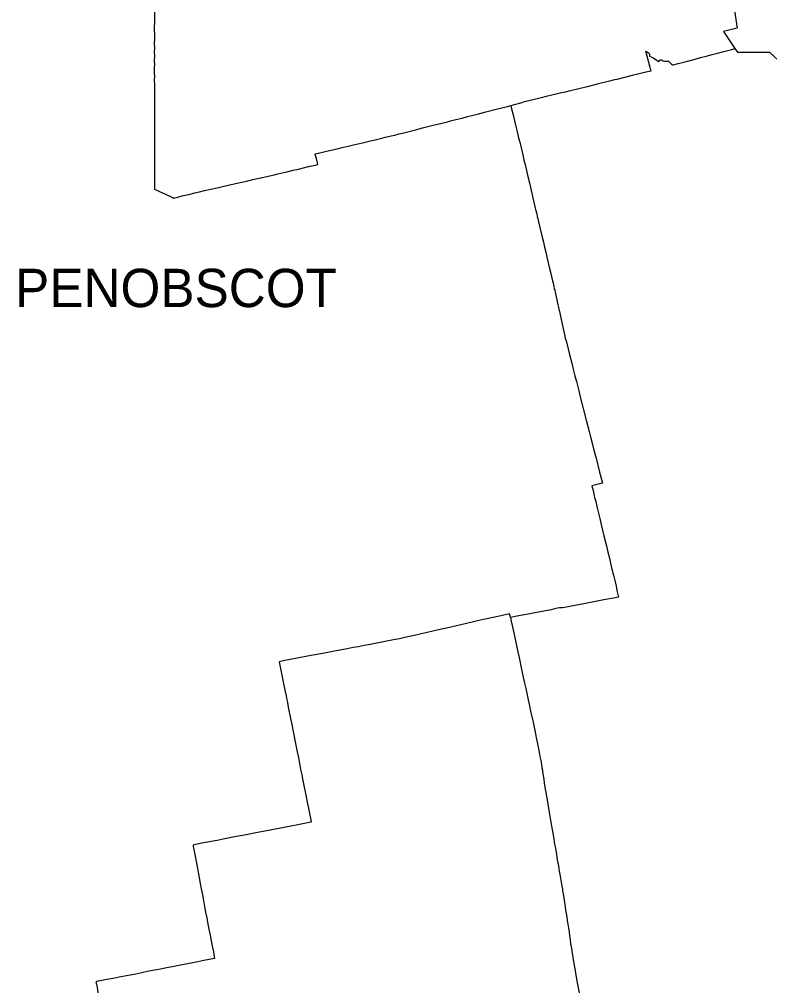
# Model space of a CAD drawing. Extents: x 1104458 to 2179854, y 15641624 to 17244911.
# Drawn here: x 1748405 to 1955164, y 16340321 to 16606552 of the extents above; entities that cross this region are included whole.
import ezdxf

# ---------------------------------------------------------------- set-up
doc = ezdxf.new("R2010")
doc.units = 0
doc.layers.add('ANNOTATION', color=7, linetype='Continuous')
doc.layers.add('CO BORDER', color=7, linetype='Continuous')

msp = doc.modelspace()

# ---------------------------------------------------------------- linework, layer by layer
at = {"layer": 'CO BORDER'}
msp.add_line((1909105, 16478728), (1906145, 16478068), dxfattribs=at)
for points in [[(1945334, 16632107), (1945226, 16630943), (1944313, 16630103), (1945087, 16625706), (1948488, 16623991), (1948540, 16623807), (1951451, 16616973), (1944329, 16616169), (1946216, 16604113), (1942463, 16603170), (1945597, 16598477)], [(1785548, 16625497), (1785552, 16624453), (1785582, 16622061), (1785592, 16618508), (1785601, 16617019), (1785608, 16613751), (1785598, 16612524), (1785621, 16610598), (1785629, 16609315), (1785620, 16605939), (1785599, 16604204), (1785628, 16601828), (1785622, 16600978), (1785593, 16599961), (1785608, 16598679), (1785605, 16597642), (1785618, 16596510), (1785604, 16595007), (1785614, 16594184), (1785600, 16593232), (1785583, 16592573), (1785596, 16592215)], [(1920987, 16597803), (1921302, 16596494), (1922109, 16593390), (1922410, 16592310), (1921539, 16592107), (1920286, 16591795), (1918844, 16591428), (1917276, 16591054), (1915568, 16590634), (1913011, 16590014)], [(1920987, 16597803), (1921258, 16597701), (1921889, 16597268), (1921965, 16597169), (1922018, 16596992), (1922024, 16596477), (1922083, 16596428), (1922914, 16596037), (1923283, 16595834), (1923645, 16595581), (1923788, 16595444), (1924150, 16595198), (1924420, 16594968), (1924537, 16594961), (1924669, 16595020), (1924915, 16595299), (1925073, 16595385), (1925272, 16595421), (1925373, 16595404), (1925826, 16595135), (1926160, 16595066), (1927019, 16595050), (1927286, 16594988), (1927463, 16594866), (1928139, 16594200), (1928379, 16593990), (1928551, 16594026), (1929986, 16594381), (1931470, 16594781), (1934637, 16595606), (1936071, 16595990), (1937704, 16596413), (1939321, 16596849), (1940772, 16597214), (1942173, 16597578), (1944776, 16598277), (1945597, 16598477)], [(1945597, 16598477), (1946273, 16597463), (1955132, 16597486), (1958877, 16593975)], [(1785596, 16592215), (1785585, 16591733), (1785613, 16590850), (1785601, 16589758), (1785633, 16588482), (1785627, 16587632), (1785634, 16586356), (1785619, 16584830), (1785632, 16581703), (1785641, 16578294), (1785638, 16577110), (1785655, 16575135), (1785646, 16573760), (1785656, 16570942), (1785648, 16568790), (1785662, 16567658), (1785650, 16566598), (1785653, 16565647), (1785669, 16564331), (1785661, 16563029), (1785680, 16561454), (1785672, 16560036), (1785684, 16559780), (1785835, 16559698), (1786521, 16559390), (1787183, 16559055)], [(1913011, 16590014), (1912400, 16589866), (1911065, 16589528), (1907955, 16588754), (1906222, 16588311), (1904853, 16587989), (1901843, 16587241), (1900233, 16586858), (1898771, 16586497), (1897459, 16586185), (1896293, 16585929), (1893569, 16585247), (1892166, 16584912), (1890687, 16584587), (1889175, 16584220), (1887267, 16583705)], [(1883855, 16582789), (1884808, 16583052), (1886992, 16583603), (1887267, 16583705)], [(1853530, 16575119), (1854714, 16575381), (1857968, 16576221), (1859530, 16576615), (1860941, 16576989), (1862461, 16577359), (1865990, 16578249), (1866398, 16578337), (1867187, 16578541), (1868656, 16578931), (1870392, 16579361), (1871911, 16579771), (1873481, 16580181), (1875001, 16580558), (1876628, 16580978), (1879767, 16581756), (1881030, 16582081), (1882931, 16582579), (1883855, 16582789)], [(1883855, 16582789), (1884057, 16581917), (1884461, 16580237), (1884847, 16578600), (1885232, 16577071), (1885592, 16575575), (1885995, 16573937), (1886286, 16572664), (1886758, 16570785), (1887119, 16569256), (1887428, 16567776), (1887760, 16566546), (1888542, 16563212), (1888963, 16561467), (1889245, 16560204), (1890387, 16555332), (1890660, 16554118), (1890965, 16552996), (1891125, 16552215), (1891257, 16551624), (1891362, 16551217)], [(1830654, 16566541), (1830584, 16566980), (1830253, 16568188), (1830043, 16569034), (1829962, 16569457), (1830369, 16569572), (1831532, 16569861), (1832703, 16570143), (1833891, 16570422), (1836026, 16570898), (1837330, 16571206), (1838999, 16571593), (1840511, 16571934), (1842106, 16572305), (1842978, 16572515), (1844041, 16572786), (1845179, 16573052), (1846425, 16573367), (1848277, 16573823), (1849257, 16574042), (1850088, 16574236), (1850840, 16574430)], [(1850840, 16574430), (1851857, 16574663), (1853077, 16574977), (1853530, 16575119)], [(1819674, 16564011), (1822141, 16564562), (1823819, 16564966), (1825289, 16565301), (1828437, 16566055), (1830041, 16566416), (1830654, 16566541)], [(1790819, 16557348), (1791275, 16557394), (1792080, 16557587), (1793575, 16557981), (1795129, 16558332), (1796739, 16558726), (1798085, 16559044), (1799472, 16559408), (1801159, 16559772), (1802929, 16560117), (1804415, 16560494), (1808760, 16561495), (1810629, 16561918), (1811393, 16562059), (1812755, 16562410), (1815347, 16563017), (1816601, 16563296), (1818637, 16563739), (1819674, 16564011)], [(1787183, 16559055), (1787719, 16558813), (1788699, 16558357), (1790425, 16557518), (1790702, 16557374), (1790819, 16557348)], [(1891362, 16551217), (1891493, 16550751), (1891861, 16549231), (1892493, 16546554), (1892844, 16545123), (1893144, 16543768), (1893477, 16542374), (1893794, 16540986), (1894129, 16539480), (1894514, 16537908), (1894823, 16536527), (1895218, 16534900), (1895480, 16533850), (1895674, 16532987), (1895814, 16532429), (1895945, 16531947), (1896072, 16531412), (1896533, 16529253), (1896800, 16527902), (1897038, 16526753), (1897403, 16525228), (1897706, 16523824), (1898607, 16519723)], [(1898607, 16519723), (1898845, 16518696), (1899141, 16517665), (1899912, 16514588), (1900735, 16511428), (1901061, 16510146), (1901506, 16508361), (1901931, 16506753), (1902294, 16505316), (1902558, 16504220), (1903057, 16502222), (1904607, 16496100), (1905422, 16492957), (1905785, 16491517), (1906219, 16489824), (1906661, 16488183), (1907314, 16485618), (1908200, 16482186), (1908808, 16479788), (1909105, 16478728)], [(1906145, 16478068), (1906483, 16476773), (1906921, 16474827), (1907218, 16473708), (1907536, 16472330), (1908368, 16469026), (1908750, 16467356), (1909502, 16464295), (1909911, 16462550), (1910271, 16461156), (1910583, 16459712), (1910982, 16458068), (1911333, 16456733), (1911708, 16455053), (1912098, 16453403), (1912461, 16451926), (1912824, 16450371), (1913162, 16448846), (1913540, 16447389)], [(1913540, 16447389), (1913018, 16447277), (1912155, 16447110), (1910479, 16446818), (1909011, 16446497), (1903958, 16445552), (1901445, 16445066), (1899629, 16444705), (1898085, 16444423), (1897425, 16444436), (1897140, 16444384)], [(1883704, 16441775), (1883616, 16442231), (1883511, 16442737), (1881061, 16442223), (1879417, 16441862), (1876272, 16441190), (1874687, 16440819), (1873168, 16440481), (1870097, 16439753), (1868511, 16439392), (1866975, 16439031), (1863903, 16438329), (1862317, 16437981), (1860756, 16437623), (1859236, 16437266), (1857650, 16436915), (1854594, 16436206), (1853165, 16435885), (1851521, 16435609)], [(1897140, 16444384), (1896280, 16444197), (1894956, 16443895), (1889957, 16442947), (1888635, 16442704), (1887066, 16442405), (1885483, 16442123), (1883704, 16441775)], [(1883704, 16441775), (1883957, 16440778), (1884647, 16437523), (1884928, 16436254), (1885679, 16432700), (1885960, 16431427), (1886299, 16429813), (1886597, 16428343), (1887275, 16425282), (1887623, 16423688), (1887962, 16422198), (1888310, 16420473), (1888649, 16419049), (1888989, 16417408), (1889295, 16415961), (1889957, 16412950), (1890629, 16409698), (1890850, 16408586), (1891070, 16407431), (1891527, 16405138), (1891821, 16403484), (1892063, 16402336), (1892247, 16401286), (1892423, 16400341), (1892525, 16399678), (1892542, 16399498)], [(1851521, 16435609), (1849660, 16435238), (1848289, 16434976), (1845098, 16434339), (1843420, 16434024), (1841824, 16433716), (1840403, 16433467), (1838766, 16433165), (1837262, 16432850), (1835675, 16432558), (1833855, 16432197), (1832467, 16431947), (1830972, 16431665), (1829368, 16431373), (1827806, 16431063), (1824532, 16430430), (1821607, 16429876), (1820020, 16429584)], [(1820020, 16429584), (1820320, 16428120), (1820668, 16426339), (1821602, 16421723), (1821890, 16420190), (1822137, 16419072), (1822258, 16418301)], [(1822258, 16418301), (1822527, 16417016), (1823130, 16413958), (1823462, 16412236), (1823767, 16410851), (1824701, 16406130), (1824989, 16404762), (1825304, 16403164), (1825924, 16399923), (1826254, 16398440), (1826552, 16396875), (1826832, 16395484), (1827171, 16393748), (1827460, 16392318), (1827765, 16390917), (1828088, 16389194), (1828361, 16387800), (1828717, 16386028), (1828844, 16385362)], [(1892542, 16399498), (1892560, 16399186), (1892905, 16397205), (1893063, 16396076), (1893434, 16394029), (1893769, 16392044), (1894239, 16389170), (1894538, 16387542), (1894863, 16385354), (1895323, 16382756), (1895571, 16381299), (1895896, 16379261), (1896110, 16378175), (1896394, 16376423), (1896644, 16375000), (1896931, 16373300), (1897182, 16371879), (1897434, 16370518), (1897727, 16368802), (1897907, 16367696), (1898041, 16366929), (1898087, 16366453)], [(1828844, 16385362), (1828244, 16385267), (1826514, 16384909), (1821856, 16384020), (1815551, 16382803), (1813995, 16382514), (1810926, 16381898), (1809387, 16381599), (1807707, 16381291), (1804555, 16380667), (1802950, 16380359), (1801311, 16380023), (1799730, 16379731), (1798241, 16379448), (1796311, 16379065)], [(1796311, 16379065), (1796346, 16378628), (1796500, 16377864), (1797103, 16374606), (1797681, 16371560), (1797988, 16369991), (1798260, 16368459), (1798542, 16366966), (1798856, 16365385), (1799155, 16363764), (1799438, 16362173), (1799738, 16360549), (1800039, 16359030), (1800360, 16357242), (1800630, 16355903), (1800956, 16354223), (1801235, 16352698), (1801500, 16351333), (1801872, 16349604), (1802004, 16348895), (1802022, 16348695), (1802202, 16347826)], [(1898087, 16366453), (1898247, 16365646), (1898807, 16362020), (1898939, 16361079), (1899254, 16359268), (1899373, 16358303), (1899542, 16357299), (1899689, 16356200), (1899868, 16355121), (1900031, 16354038), (1900176, 16353047), (1900322, 16351968), (1900609, 16350088), (1900641, 16349730), (1902117, 16341138), (1903646, 16333342)], [(1802202, 16347826), (1799236, 16347229), (1797594, 16346917), (1796203, 16346622), (1794711, 16346336), (1791453, 16345680), (1788121, 16345040), (1786837, 16344784), (1785079, 16344459), (1783696, 16344187), (1782179, 16343875), (1780547, 16343531), (1778922, 16343219), (1775905, 16342662), (1774256, 16342343), (1772564, 16342032), (1771131, 16341746), (1770073, 16341523), (1769523, 16341402)], [(1769523, 16341402), (1769629, 16340742), (1769809, 16339932), (1769989, 16338990), (1770423, 16336795), (1770653, 16335562), (1770980, 16333875), (1771267, 16332448), (1771635, 16330539), (1771995, 16328613), (1772143, 16327993)]]:
    msp.add_lwpolyline(points, dxfattribs=at)

# ---------------------------------------------------------------- texts
at = {"layer": 'ANNOTATION'}
msp.add_text('PENOBSCOT', height=10560.2, dxfattribs=at).set_placement((1747247, 16527265))

doc.saveas('drawing.dxf')
